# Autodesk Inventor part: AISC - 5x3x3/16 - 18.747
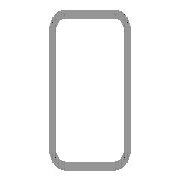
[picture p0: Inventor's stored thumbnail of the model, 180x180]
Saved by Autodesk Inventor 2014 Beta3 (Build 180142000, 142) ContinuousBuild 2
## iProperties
Created: 2013-01
Part Number: AISC - 5x3x3/16 - 18.747
Material: Steel, Mild
Description: Tube
Document SubType Name: Modeling
Standard: ANSI
Designer: Thomas
Standards Organization: ANSI
Language: en-US
Size Designation: 5x3x3/16
Categories: <MemberInstance><Categories><Category DisplayName="Structural Shapes" InternalName="089c4875-fa83-4c05-b084-43b9cc11f5ed" Mnemonic="GRDR"><CategoryParameter Dis
Stock Number: 5x3x3/16
Density: 7.86 g/cm^3
Appearance: Steel
IsCustomPart: 1
_CCFamilyMember: 33
_CCFamilyDisplayName: ANSI AISC (Rectangular) - Tube
_FrameMemberDoc: Frame Member File
_Version: 15.0.0
_GetPNFromCC: 1
Author: Thomas
G_L: 18.747 in
G_W: 3.000 in
G_H: 5.000 in
+81598EE7-2C8A-4684-9D57-2FF5DF881D44+CUTDETAIL1: Cut
+9951DD3C-6153-424A-A551-3E22ECA78F0B+CUTDETAIL2: Cut
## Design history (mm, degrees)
node "Start plane"
node "End plane"
node "Driven Length"
  sketch "Sketch3"
    geometry: L1 (0, 0)-(10, 0) reference
    constraints: 2 end point, 1 horizontal
  workplane "Work Plane3"
  sketch "Sketch4"
    geometry: L1 (-2, 0)-(12, 0) reference; L2 (-53.343, 476.185)-(53.343, 476.185) reference
    dimensions: "d19" = 476.18539 distance between parallel lines of L1 L2 (derived)
sketch "Sweep Path"
  geometry: L1 through (609.6, 0) direction (1, 0); 1 other entity
  constraints: 5 horizontal
node "Orientation Work Plane"
feature "Body" dims "d20" = 0
workplane "Work Plane5"
sketch "Sketch5"
  geometry: L1 (-38.6, 73.96)-(38.6, 73.96); L2 (-38.6, -73.96)-(38.6, -73.96)
  constraints: 4 end point
feature "LoftSrf1" sketch "Sketch5" dims "d21" = 0, "d22" = 90 deg, "d23" = 0, "d24" = 90 deg
split "Split1"
workplane "Work Plane6"
sketch "Sketch6"
  geometry: L1 (-38.6, 73.96)-(38.6, 73.96); L2 (-38.6, -73.96)-(38.6, -73.96)
  constraints: 4 end point
feature "LoftSrf2" sketch "Sketch6" dims "d25" = 0, "d26" = 90 deg, "d27" = 0, "d28" = 90 deg
split "Split2"
body "Solid1"
sketch "Sketch"
  geometry: L1 (-38.1, -53.975)-(-38.1, 53.975); L2 (-28.575, 63.5)-(28.575, 63.5); L3 (38.1, 53.975)-(38.1, -53.975); L4 (28.575, -63.5)-(-28.575, -63.5); L5 (-28.575, 58.737)-(28.575, 58.737); L6 (33.338, 53.975)-(33.338, -53.975); L7 (28.575, -58.737)-(-28.575, -58.737); L8 (-33.338, -53.975)-(-33.338, 53.975); L9 (0, 36.948)-(0, -36.948); L10 (-23.079, 0)-(23.079, 0); A1 r 9.525 centre (-28.575, -53.975) between (-38.1, -53.975) and (-28.575, -63.5); A2 r 9.525 centre (-28.575, 53.975) between (-28.575, 63.5) and (-38.1, 53.975); A3 r 9.525 centre (28.575, 53.975) between (38.1, 53.975) and (28.575, 63.5); A4 r 9.525 centre (28.575, -53.975) between (28.575, -63.5) and (38.1, -53.975); A5 r 4.763 centre (-28.575, 53.975) between (-28.575, 58.737) and (-33.338, 53.975); A6 r 4.763 centre (28.575, 53.975) between (33.338, 53.975) and (28.575, 58.737); A7 r 4.763 centre (28.575, -53.975) between (28.575, -58.737) and (33.338, -53.975); A8 r 4.763 centre (-28.575, -53.975) between (-33.338, -53.975) and (-28.575, -58.737)
  constraints: 20 end point, 16 point on circle, 8 centre point, 8 tangent, 4 parallel, 3 equal radius, 2 perpendicular, 7 other
  dimensions: "d10" = 127 distance between parallel lines of L2 L4 (= G_H); "d11" = 76.2 distance between parallel lines of L1 L3 (= G_W); "d12" = 4.7625 distance between parallel lines of L3 L6 (= G_T); "d15" = 63.5 distance between parallel lines of L2 L10 (= 0.5 x d10); "d16" = 38.1 distance between parallel lines of L9 L3 (= 0.5 x d11); "d17" = 9.525 radius of A1 (= G_IR)
body "Srf1"
body "Srf2"
other parameters: "G_W" = 76.2 [user parameter; used in 1 equation term], "G_H" = 127 [user parameter; used in 1 equation term], "G_T" = 4.7625 [user parameter; used in 1 equation term], "G_IR" = 9.525 [user parameter; used in 1 equation term], "G_L" = 476.18539 (= d19) [user parameter], "G_OFFSET_START" = 0 [user parameter; used in 1 equation term], "G_OFFSET_END" = 0 [user parameter; used in 1 equation term], "d13" = 0 (computed from G_OFFSET_START), "d14" = 476.18539 (= G_OFFSET_END + B_L), "B_L" = 476.18539 [user parameter; used in 1 equation term], "d18" = 90 deg
